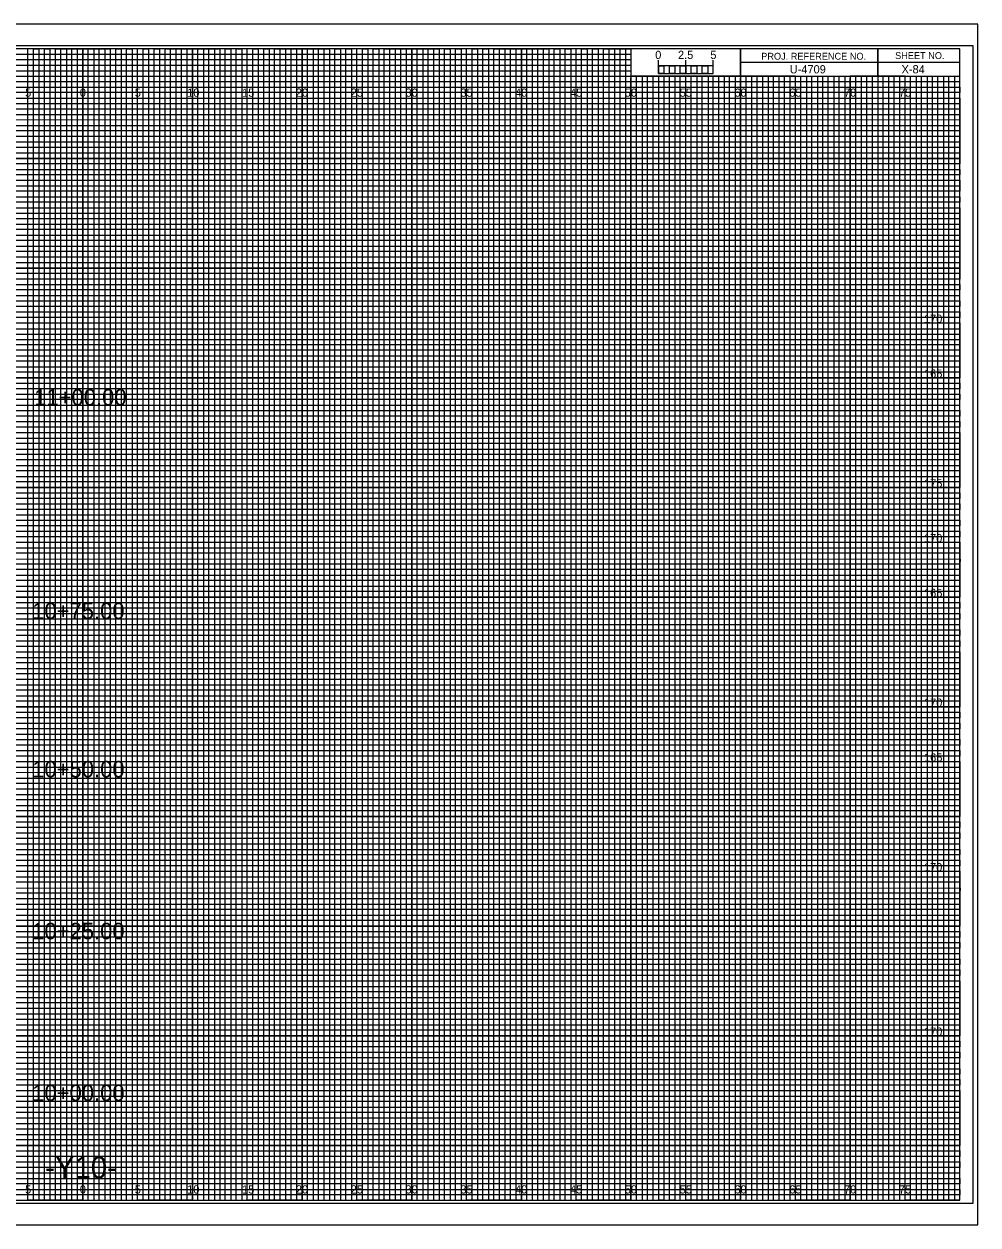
# Model space of a CAD drawing. Extents: x -7 to 162, y -2 to 107.
# Drawn here: x 74.6 to 161.7, y -2.3 to 107.3 of the extents above; entities that cross this region are included whole.
import ezdxf

# ---------------------------------------------------------------- set-up
doc = ezdxf.new("R2010")
doc.units = 0
for name, color, linetype in [('Prop XS Alignment Label', 7, 'Continuous'), ('Prop XS Bar Scale Labels', 7, 'Continuous'), ('Prop XS Earthwork Shape', 7, 'Continuous'), ('Prop XS Elevation Labels', 7, 'Continuous'), ('Prop XS Project Number', 7, 'Continuous'), ('Prop XS Sheet Number', 7, 'Continuous'), ('Prop XS Station Labels', 7, 'Continuous'), ('Sheet Cross Section CELL', 7, 'Continuous'), ('Sheet Cross Section Grid Major CELL', 7, 'Continuous'), ('Sheet Cross Section Grid Middle CELL', 7, 'Continuous'), ('Sheet Cross Section Grid Minor 1 CELL', 7, 'Continuous'), ('Sheet Cross Section Grid Minor 2 CELL', 7, 'Continuous'), ('Sheet Cross Section Scale CELL', 7, 'Continuous'), ('Sheet Cutting Line CELL', 7, 'Continuous'), ('Sheet DOT Grid CELL', 7, 'Continuous'), ('Sheet Plot Border Inside CELL', 7, 'Continuous'), ('Sheet Plot Border Outside CELL', 7, 'Continuous')]:
    doc.layers.add(name, color=color, linetype=linetype)

msp = doc.modelspace()

# ---------------------------------------------------------------- linework, layer by layer
at = {"layer": 'Sheet Cross Section CELL'}
for p, q in [((152.5, 105), (152.5, 102.5)), ((152.5, 102.5), (152.5, 105)), ((160, 103.75), (140, 103.75)), ((140, 103.75), (140, 102.5)), ((140, 102.5), (160, 102.5))]:
    msp.add_line(p, q, dxfattribs=at)
for points in [[(160, 105), (0, 105), (0, 0), (160, 0)], [(140, 105), (130, 105), (130, 102.52), (140, 102.52)], [(160, 105), (140, 105), (140, 102.5), (160, 102.5)]]:
    msp.add_lwpolyline(points, close=True, dxfattribs=at)
at = {"layer": 'Sheet Cross Section Grid Major CELL'}
for p, q in [((75, 105), (70, 105)), ((75, 0), (75, 105)), ((85, 105), (80, 105)), ((80, 105), (80, 0)), ((85, 0), (85, 105)), ((95, 105), (90, 105)), ((90, 105), (90, 0)), ((95, 0), (95, 105)), ((105, 105), (100, 105)), ((100, 105), (100, 0)), ((105, 0), (105, 105)), ((115, 105), (110, 105)), ((110, 105), (110, 0)), ((115, 0), (115, 105)), ((125, 105), (120, 105)), ((120, 105), (120, 0)), ((125, 0), (125, 105)), ((130, 105), (130, 0)), ((135, 0), (135, 102.5)), ((145, 102.5), (140, 102.5)), ((140, 102.5), (140, 0)), ((145, 0), (145, 102.5)), ((155, 102.5), (150, 102.5)), ((150, 102.5), (150, 0)), ((155, 0), (155, 102.5)), ((80, 0), (75, 0)), ((90, 0), (85, 0)), ((100, 0), (95, 0)), ((110, 0), (105, 0)), ((120, 0), (115, 0)), ((130, 0), (125, 0)), ((140, 0), (135, 0)), ((150, 0), (145, 0)), ((160, 0), (155, 0)), ((160, 0), (160, 0))]:
    msp.add_line(p, q, dxfattribs=at)
for points in [[(0, 100), (160, 100), (160, 95), (0, 95)], [(0, 90), (160, 90), (160, 85), (0, 85)], [(0, 80), (160, 80), (160, 75), (0, 75)], [(0, 70), (160, 70), (160, 65), (0, 65)], [(0, 60), (160, 60), (160, 55), (0, 55)], [(0, 50), (160, 50), (160, 45), (0, 45)], [(0, 40), (160, 40), (160, 35), (0, 35)], [(0, 30), (160, 30), (160, 25), (0, 25)], [(0, 20), (160, 20), (160, 15), (0, 15)], [(0, 10), (160, 10), (160, 5), (0, 5)]]:
    msp.add_lwpolyline(points, dxfattribs=at)
at = {"layer": 'Sheet Cross Section Grid Middle CELL'}
for points in [[(72.5, 0), (77.5, 0), (77.5, 105), (82.5, 105), (82.5, 0), (87.5, 0), (87.5, 105), (92.5, 105), (92.5, 0), (97.5, 0), (97.5, 105), (102.5, 105), (102.5, 0), (107.5, 0), (107.5, 105), (112.5, 105), (112.5, 0), (117.5, 0), (117.5, 105), (122.5, 105), (122.5, 0), (127.5, 0), (127.5, 105), (129.97, 105), (130, 105), (130, 102.5), (132.5, 102.5), (132.5, 0), (137.5, 0), (137.5, 102.5), (142.5, 102.5), (142.5, 0), (147.5, 0), (147.5, 102.5), (152.5, 102.5), (152.5, 0), (157.5, 0), (157.5, 102.5)], [(0, 102.5), (137.5, 102.5)], [(0, 92.5), (160, 92.5), (160, 97.5), (0, 97.5)], [(0, 82.5), (160, 82.5), (160, 87.5), (0, 87.5)], [(0, 72.5), (160, 72.5), (160, 77.5), (0, 77.5)], [(0, 62.5), (160, 62.5), (160, 67.5), (0, 67.5)], [(0, 52.5), (160, 52.5), (160, 57.5), (0, 57.5)], [(0, 42.5), (160, 42.5), (160, 47.5), (0, 47.5)], [(0, 32.5), (160, 32.5), (160, 37.5), (0, 37.5)], [(0, 22.5), (160, 22.5), (160, 27.5), (0, 27.5)], [(0, 12.5), (160, 12.5), (160, 17.5), (0, 17.5)], [(0, 2.5), (160, 2.5), (160, 7.5), (0, 7.5)]]:
    msp.add_lwpolyline(points, dxfattribs=at)
at = {"layer": 'Sheet Cross Section Grid Minor 1 CELL'}
for p, q in [((0, 104.5), (130, 104.5)), ((130, 104.5), (130, 103.99)), ((130, 103.99), (0, 103.99)), ((0, 103.5), (130, 103.5)), ((130, 102.95), (0, 102.95)), ((130, 103.5), (130, 102.95)), ((0, 102), (160, 102))]:
    msp.add_line(p, q, dxfattribs=at)
for points in [[(0, 101.5), (135, 101.5), (160, 101.5), (160, 101), (0, 101)], [(0, 100.5), (160, 100.5), (160, 99.5), (0, 99.5)], [(0, 99), (160, 99), (160, 98.5), (0, 98.49)], [(0, 98), (160, 98), (160, 97), (0, 97)], [(0, 96.5), (160, 96.5), (160, 96), (0, 96)], [(0, 95.5), (160, 95.5), (160, 94.5), (0, 94.5)], [(0, 94), (160, 94), (160, 93.5), (0, 93.5)], [(0, 93), (160, 93), (160, 92), (0, 92)], [(0, 91.5), (160, 91.5), (160, 91), (0, 91)], [(0, 90.5), (160, 90.5), (160, 89.5), (0, 89.5)], [(0, 89), (160, 89), (160, 88.5), (0, 88.5)], [(0, 88), (160, 88), (160, 86.98), (160, 86.5), (160, 86), (0, 86)], [(0, 87), (160, 87), (160, 86.5), (0, 86.5)], [(0, 85.5), (160, 85.5), (160, 84.5), (0, 84.52)], [(0, 84.52), (160, 84.5), (160, 84), (0, 84)], [(0, 83.5), (160, 83.5), (160, 83), (0, 83)], [(0, 82), (160, 82), (160, 81.5), (0, 81.5)], [(0, 81), (160, 81), (160, 80.5), (0, 80.5)], [(-0.04, 79.45), (160, 79.45), (160, 78.94), (-0.04, 78.94)], [(0, 78.5), (160, 78.5), (160, 78), (0, 78)], [(0, 77), (160, 77), (160, 76.5), (0, 76.5)], [(0, 76), (160, 76), (160, 75.5), (0, 75.5)], [(0, 74.5), (160, 74.5), (160, 74), (0, 74)], [(0, 73.5), (160, 73.5), (160, 73), (0, 73)], [(0, 72), (160, 72), (160, 71.5), (0, 71.5)], [(0, 71), (160, 71), (160, 70.5), (0, 70.5)], [(0, 69.5), (160, 69.5), (160, 68.99), (0, 69)], [(0, 68.5), (160, 68.5), (160, 68), (0, 68)], [(0, 67), (160, 67), (160, 66.5), (0, 66.5)], [(0, 66), (160, 66), (160, 65.5), (0, 65.5)], [(0, 64.5), (160, 64.5), (160, 64), (0, 64)], [(0, 63.5), (160, 63.5), (160, 63), (0, 63)], [(0, 62), (160, 62), (160, 61.5), (0, 61.5)], [(0, 61), (160, 61), (160, 60.5), (0, 60.5)], [(0, 59.5), (160, 59.5), (160, 59), (0, 59)], [(0, 58.5), (160.03, 58.45), (160, 58), (0, 58)], [(0, 57), (160, 57), (160, 56.5), (0, 56.5)], [(0, 56), (160, 56), (160, 55.5), (0, 55.5)], [(0, 54.5), (160, 54.5), (160, 54), (0, 54)], [(0, 53.5), (160, 53.5), (160, 53), (0, 53)], [(0, 52), (160, 52), (160, 51.5), (0, 51.5)], [(0, 51), (160, 51), (160, 50.5), (0, 50.5)], [(0, 49.5), (160, 49.5), (160, 49), (0, 49)], [(0, 48.5), (160, 48.5), (160, 48), (0, 48)], [(0, 47), (160, 47), (160, 46.5), (0, 46.5)], [(0, 46), (160, 46), (160, 45.5), (0, 45.5)], [(0, 44.5), (160, 44.5), (160, 44), (0, 44)], [(0, 43.5), (160, 43.5), (160, 43), (0, 43)], [(0, 42), (160, 42), (160, 41.5), (0, 41.5)], [(0, 41), (160, 41), (160, 40.5), (0, 40.5)], [(0, 39.5), (160, 39.5), (160, 38.99), (0, 39)], [(0, 38.5), (160, 38.5), (160, 38), (0, 38)], [(0, 37), (160, 37), (160, 36.5), (0, 36.5)], [(0, 36), (160, 36), (160, 35.5), (0, 35.5)], [(0, 34.5), (160, 34.5), (160, 34), (0, 34)], [(0, 33.5), (160, 33.5), (160, 33), (0, 33)], [(0, 32), (160, 32), (160, 31.5), (0, 31.5)], [(0, 31), (160, 31), (160, 30.5), (0, 30.5)], [(0, 29.5), (160, 29.5), (160, 29), (0, 29)], [(0, 28.5), (160.03, 28.46), (160, 28), (0, 28)], [(0, 27), (160, 27), (160, 26.5), (0, 26.5)], [(0, 26), (160, 26), (160, 25.5), (0, 25.5)], [(0, 24.5), (160, 24.5), (160, 24), (0, 24)], [(0, 23.5), (160, 23.5), (160, 23), (0, 23)], [(0, 22), (160, 22), (160, 21.5), (0, 21.5)], [(0, 21), (160, 21), (160, 20.5), (0, 20.5)], [(0, 19.5), (160, 19.5), (160, 19), (0, 19)], [(0, 18.5), (160, 18.5), (160, 18), (0, 18)], [(0, 17), (160, 17), (160, 16.5), (0, 16.5)], [(0, 16), (160, 16), (160, 15.5), (0, 15.5)], [(0, 14.5), (160, 14.5), (160, 14), (0, 14)], [(0, 13.5), (160, 13.5), (160, 13), (0, 13)], [(0, 12), (160, 12), (160, 11.5), (0, 11.5)], [(0, 11), (160, 11), (160, 10.5), (0, 10.5)], [(0, 9.5), (160, 9.5), (160, 9), (0, 9)], [(0, 8.5), (160, 8.5), (160, 8), (0, 8)], [(0, 7), (160, 7), (160, 6.5), (0, 6.5)], [(0, 6), (160, 6), (160, 5.5), (0, 5.5)], [(0, 4.5), (160, 4.5), (160, 4), (0, 4)], [(0, 3.5), (160, 3.5), (160, 3), (0, 3)], [(0, 2), (160, 2), (160, 1.5), (0, 1.5)], [(0, 1), (160, 1), (160, 0.5), (0, 0.5)]]:
    msp.add_lwpolyline(points, dxfattribs=at)
at = {"layer": 'Sheet Cross Section Grid Minor 2 CELL'}
for p, q in [((133.5, 102.5), (133, 102.5)), ((133, 102.5), (133, 0)), ((133.5, 0), (133.5, 102.5)), ((134.5, 102.5), (134, 102.5)), ((134, 102.5), (134, 0)), ((134.5, 0), (134.5, 102.5)), ((133, 0), (132.5, 0)), ((134, 0), (133.5, 0))]:
    msp.add_line(p, q, dxfattribs=at)
for points in [[(75, 0), (75.5, 0), (75.5, 105), (76, 105), (76, 0)], [(76, 0), (76.5, 0), (76.5, 105), (77, 105), (77, 0)], [(77.5, 0), (78, 0), (78, 105), (78.5, 105), (78.5, 0)], [(78.5, 0), (79, 0), (79, 105), (79.5, 105), (79.5, 0)], [(80, 0), (80.5, 0), (80.5, 105), (81, 105), (81, 0)], [(81, 0), (81.5, 0), (81.5, 105), (82, 105), (82, 0)], [(82.5, 0), (83, 0), (83, 105), (83.5, 105), (83.5, 0)], [(83.5, 0), (84, 0), (84, 105), (84.5, 105), (84.5, 0)], [(85, 0), (85.5, 0), (85.5, 105), (86, 105), (86, 0)], [(86, 0), (86.5, 0), (86.5, 105), (87, 105), (87, 0)], [(87.5, 0), (88, 0), (88, 105), (88.5, 105), (88.5, 0)], [(88.5, 0), (89, 0), (89, 105), (89.5, 105), (89.5, 0)], [(90, 0), (90.5, 0), (90.5, 105), (91, 105), (91, 0)], [(91, 0), (91.5, 0), (91.5, 105), (92, 105), (92, 0)], [(92.5, 0), (93, 0), (93, 105), (93.5, 105), (93.5, 0)], [(93.5, 0), (94, 0), (94, 105), (94.5, 105), (94.5, 0)], [(95, 0), (95.5, 0), (95.5, 105), (96, 105), (96, 0)], [(96, 0), (96.5, 0), (96.5, 105), (97, 105), (97, 0)], [(97.5, 0), (98, 0), (98, 105), (98.5, 105), (98.5, 0)], [(98.5, 0), (99, 0), (99, 105), (99.5, 105), (99.5, 0)], [(100, 0), (100.5, 0), (100.5, 105), (101, 105), (101, 0)], [(101, 0), (101.5, 0), (101.5, 105), (102, 105), (102, 0)], [(102.5, 0), (103, 0), (103, 105), (103.5, 105), (103.5, 0)], [(103.5, 0), (104, 0), (104, 105), (104.5, 105), (104.5, 0)], [(105, 0), (105.5, 0), (105.5, 105), (106, 105), (106, 0)], [(106, 0), (106.5, 0), (106.5, 105), (107, 105), (107, 0)], [(107.5, 0), (108, 0), (108, 105), (108.5, 105), (108.5, 0)], [(108.5, 0), (109, 0), (109, 105), (109.5, 105), (109.5, 0)], [(110, 0), (110.5, 0), (110.5, 105), (111, 105), (111, 0)], [(111, 0), (111.5, 0), (111.5, 105), (112, 105), (112, 0)], [(112.5, 0), (113, 0), (113, 105), (113.5, 105), (113.5, 0)], [(113.5, 0), (114, 0), (114, 105), (114.5, 105), (114.5, 0)], [(115, 0), (115.5, 0), (115.5, 105), (116, 105), (116, 0)], [(116, 0), (116.5, 0), (116.5, 105), (117, 105), (117, 0)], [(117.5, 0), (118, 0), (118, 105), (118.5, 105), (118.5, 0)], [(118.5, 0), (119, 0), (119, 105), (119.5, 105), (119.5, 0)], [(120, 0), (120.5, 0), (120.5, 105), (121, 105), (121, 0)], [(121, 0), (121.5, 0), (121.5, 105), (122, 105), (122, 0)], [(122.5, 0), (123, 0), (123, 105), (123.5, 105), (123.5, 0)], [(123.5, 0), (124, 0), (124, 105), (124.5, 105), (124.5, 0)], [(125, 0), (125.5, 0), (125.5, 105), (126, 105), (126, 0)], [(126, 0), (126.5, 0), (126.5, 105), (127, 105), (127, 0)], [(127.5, 0), (128, 0), (128, 105), (128.5, 105), (128.5, 0)], [(128.5, 0), (129, 0), (129, 105), (129.5, 105), (129.5, 0)], [(130, 0), (130.5, 0), (130.5, 102.5), (131.01, 102.5), (131.01, 0)], [(131, 0), (131.5, 0), (131.5, 102.5), (132, 102.5), (132, 0)], [(135, 0), (135.49, 0), (135.49, 102.5), (136, 102.5), (136, 0)], [(136, 0), (136.5, 0), (136.5, 102.5), (137.03, 102.5), (137.03, 0)], [(137.5, 0), (138, 0), (138, 102.5), (138.5, 102.5), (138.5, 0)], [(138.5, 0), (139, 0), (139, 102.5), (139.5, 102.5), (139.5, 0)], [(140, 0), (140.5, 0), (140.5, 102.5), (141, 102.5), (141, 0)], [(141, 0), (141.5, 0), (141.5, 102.5), (142, 102.5), (142, 0)], [(142.5, 0), (143, 0), (143, 102.5), (143.5, 102.5), (143.5, 0)], [(143.5, 0), (144, 0), (144, 102.5), (144.5, 102.5), (144.5, 0)], [(145, 0), (145.5, 0), (145.5, 102.5), (146, 102.5), (146, 0)], [(146, 0), (146.5, 0), (146.5, 102.5), (147, 102.5), (147, 0)], [(147.5, 0), (148, 0), (148, 102.5), (148.5, 102.5), (148.5, 0)], [(148.5, 0), (149, 0), (149, 102.5), (149.5, 102.5), (149.5, 0)], [(150, 0), (150.5, 0), (150.5, 102.5), (151, 102.5), (151, 0)], [(151, 0), (151.5, 0), (151.5, 102.5), (152, 102.5), (152, 0)], [(152.5, 0), (153, 0), (153, 102.5), (153.5, 102.5), (153.5, 0)], [(153.5, 0), (154, 0), (154, 102.5), (154.5, 102.5), (154.5, 0)], [(155, 0), (155.5, 0), (155.5, 102.5), (156, 102.5), (156, 0)], [(156, 0), (156.5, 0), (156.5, 102.5), (157, 102.5), (157, 0)], [(157.5, 0), (158, 0), (158, 102.5), (158.5, 102.5), (158.5, 0)], [(158.5, 0), (159, 0), (159, 102.5), (159.5, 102.5), (159.5, 0)]]:
    msp.add_lwpolyline(points, dxfattribs=at)
at = {"layer": 'Sheet Cross Section Scale CELL'}
for p, q in [((132.5, 102.75), (132.5, 103.95)), ((132.5, 103.45), (132.5, 103.95)), ((135, 102.75), (135, 103.95)), ((137.5, 102.75), (137.5, 103.95)), ((137.5, 103.45), (137.5, 103.95))]:
    msp.add_line(p, q, dxfattribs=at)
for points in [[(137.5, 103.45), (132.5, 103.45), (132.5, 102.75), (137.5, 102.75)], [(132.5, 103.45), (133, 103.45), (133, 102.75), (132.5, 102.75)], [(133.5, 103.45), (134, 103.45), (134, 102.75), (133.5, 102.75)], [(134.5, 103.45), (135, 103.45), (135, 102.75), (134.5, 102.75)], [(135.5, 103.45), (136, 103.45), (136, 102.75), (135.5, 102.75)], [(136.5, 103.45), (137, 103.45), (137, 102.75), (136.5, 102.75)]]:
    msp.add_lwpolyline(points, close=True, dxfattribs=at)
at = {"layer": 'Sheet Cutting Line CELL'}
for p, q in [((161.65, 107.25), (-6.7, 107.25)), ((-6.7, -2.25), (161.65, -2.25))]:
    msp.add_line(p, q, dxfattribs=at)
at = {"layer": 'Sheet DOT Grid CELL'}
for p, q in [((75, 0), (75, 105)), ((80, 0), (80, 105)), ((85, 0), (85, 105)), ((90, 0), (90, 105)), ((95, 0), (95, 105)), ((100, 0), (100, 105)), ((105, 0), (105, 105)), ((110, 0), (110, 105)), ((115, 0), (115, 105)), ((120, 0), (120, 105)), ((125, 0), (125, 105)), ((130, 0), (130, 102.34)), ((135, 0), (135, 102.34)), ((140, 0), (140, 102.34)), ((145, 0), (145, 102.34)), ((150, 0), (150, 102.34)), ((155, 0), (155, 102.34)), ((0, 100), (160, 100)), ((0, 95), (160, 95)), ((0, 90), (160, 90)), ((0, 85), (160, 85)), ((0, 80), (160, 80)), ((0, 75), (160, 75)), ((0, 70), (160, 70)), ((0, 65), (160, 65)), ((0, 60), (160, 60)), ((0, 55), (160, 55)), ((0, 50), (160, 50)), ((0, 45), (160, 45)), ((0, 40), (160, 40)), ((0, 35), (160, 35)), ((0, 30), (160, 30)), ((0, 25), (160, 25)), ((0, 20), (160, 20)), ((0, 15), (160, 15)), ((0, 10), (160, 10)), ((0, 5), (160, 5))]:
    msp.add_line(p, q, dxfattribs=at)
at = {"layer": 'Sheet Plot Border Inside CELL'}
msp.add_lwpolyline([(-5.4, -0.25), (161.2, -0.25), (161.2, 105.25), (-5.4, 105.25)], close=True, dxfattribs=at)
at = {"layer": 'Sheet Plot Border Outside CELL'}
msp.add_lwpolyline([(-6.7, -2.25), (161.65, -2.25), (161.65, 107.25), (-6.7, 107.25)], close=True, dxfattribs=at)

# ---------------------------------------------------------------- texts
at = {"layer": 'Prop XS Alignment Label'}
msp.add_text('-Y10-', height=2, dxfattribs=at).set_placement((76.57, 2))
at = {"layer": 'Prop XS Bar Scale Labels'}
for s, p in [('2.5', (134.29, 104.06)), ('5', (137.24, 104.06))]:
    msp.add_text(s, height=0.75, dxfattribs=at).set_placement(p)
at = {"layer": 'Prop XS Earthwork Shape'}
for s, p in [('5', (74.74, 100.62)), ('0', (79.73, 100.62)), ('0', (79.73, 100.62)), ('5', (84.74, 100.62)), ('10', (89.52, 100.62)), ('15', (94.53, 100.62)), ('20', (99.43, 100.62)), ('25', (104.44, 100.62)), ('30', (109.43, 100.62)), ('35', (114.44, 100.62)), ('40', (119.43, 100.62)), ('45', (124.44, 100.62)), ('50', (129.43, 100.62)), ('55', (134.44, 100.62)), ('60', (139.43, 100.62)), ('65', (144.44, 100.62)), ('70', (149.43, 100.62)), ('75', (154.44, 100.62)), ('5', (74.74, 0.62)), ('0', (79.73, 0.62)), ('0', (79.73, 0.62)), ('5', (84.74, 0.62)), ('10', (89.52, 0.62)), ('15', (94.53, 0.62)), ('20', (99.43, 0.62)), ('25', (104.44, 0.62)), ('30', (109.43, 0.62)), ('35', (114.44, 0.62)), ('40', (119.43, 0.62)), ('45', (124.44, 0.62)), ('50', (129.43, 0.62)), ('55', (134.44, 0.62)), ('60', (139.43, 0.62)), ('65', (144.44, 0.62)), ('70', (149.43, 0.62)), ('75', (154.44, 0.62))]:
    msp.add_text(s, height=0.75, dxfattribs=at).set_placement(p)
at = {"layer": 'Prop XS Elevation Labels'}
for s, p in [('170', (156.72, 80)), ('165', (156.73, 75)), ('175', (156.73, 65)), ('170', (156.72, 60)), ('165', (156.73, 55)), ('170', (156.72, 45)), ('165', (156.73, 40)), ('170', (156.72, 30)), ('170', (156.72, 15))]:
    msp.add_text(s, height=0.75, dxfattribs=at).set_placement(p)
at = {"layer": 'Prop XS Project Number'}
msp.add_text('U-4709', height=0.75, dxfattribs=at).set_placement((144.48, 102.75))
at = {"layer": 'Prop XS Sheet Number'}
msp.add_text('X-84', height=0.75, dxfattribs=at).set_placement((154.68, 102.75))
at = {"layer": 'Prop XS Station Labels'}
for s, p in [('11+00.00', (75.57, 72.47)), ('10+75.00', (75.39, 52.99)), ('10+50.00', (75.39, 38.56)), ('10+25.00', (75.39, 23.8)), ('10+00.00', (75.39, 9.05))]:
    msp.add_text(s, height=1.5, dxfattribs=at).set_placement(p)
at = {"layer": 'Sheet Cross Section CELL'}
for s, p in [('PROJ. REFERENCE NO.', (141.88, 104)), ('SHEET NO.', (154.09, 104.06))]:
    msp.add_text(s, height=0.625, dxfattribs=at).set_placement(p)
at = {"layer": 'Sheet Cross Section Scale CELL'}
msp.add_text('0', height=0.75, dxfattribs=at).set_placement((132.21, 104.06))

doc.saveas('drawing.dxf')
